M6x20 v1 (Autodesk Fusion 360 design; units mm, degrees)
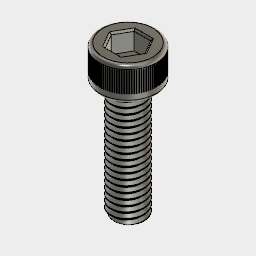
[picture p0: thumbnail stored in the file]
sketch "スケッチ1"
  circle C1 centre (0, 0) radius 3
  circle C2 centre (0, 0) radius 5
  dimension "d1" diameter C1 = 6
  dimension "d2" diameter C2 = 10
extrude "押し出し1" new body sketch "スケッチ1" blind 5.8
sketch "スケッチ2" plane through (0, 0, 5.8) normal (0, 0, 1) x axis (-1, 0, 0)
  line L1 (-1.4722, -2.55) -> (-2.9445, 0)
  line L2 (1.4722, -2.55) -> (-1.4722, -2.55)
  line L3 (2.9445, 0) -> (1.4722, -2.55)
  line L4 (1.4722, 2.55) -> (2.9445, 0)
  line L5 (-1.4722, 2.55) -> (1.4722, 2.55)
  line L6 (-2.9445, 0) -> (-1.4722, 2.55)
  circle C1 centre (0, 0) radius 5
  dimension "d5" distance L2 L5 = 5.1
work_plane "作業平面" sketch "スケッチ2" AlongDistance -0.75
extrude "押し出し2" cut sketch "スケッチ2" profile of L1 L2 L3 L4 L5 L6 against normal blind 3.3
chamfer "面取り" distance 0.3
sketch "スケッチ3" plane through (0, 0, 5.05) normal (0, 0, 1) x axis (1, 0, 0)
  line L1 (-0.05, 4.9497) -> (-0.05, 4.9997)
  line L2 (0.05, 4.9497) -> (-0.05, 4.9497)
  line L3 (0.05, 4.9997) -> (0.05, 4.9497)
  circle C1 centre (0, 0) radius 5
  point P4 (-0.05, 4.9497)
  point P5 (0.05, 4.9497)
  point P3 (-0.05, 4.9997)
  point P6 (0.05, 4.9997)
  dimension "d18" distance P4 P5 = 0.1
  dimension "d19" distance P3 P4 = 0.05
  dimension "d20" distance P5 P6 = 0.05 (= "d19")
extrude "押し出し3" cut sketch "スケッチ3" against normal blind 3.6
work_axis "作業軸"
circular_pattern "C パターン" countU 100 TotalAngle 360
fillet "フィレット1" radius 0.6
extrude "押し出し4" add sketch "スケッチ1" profile of C1 blind -20
thread "ねじ"
fillet "フィレット2" sketch "スケッチ3" radius 0.5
